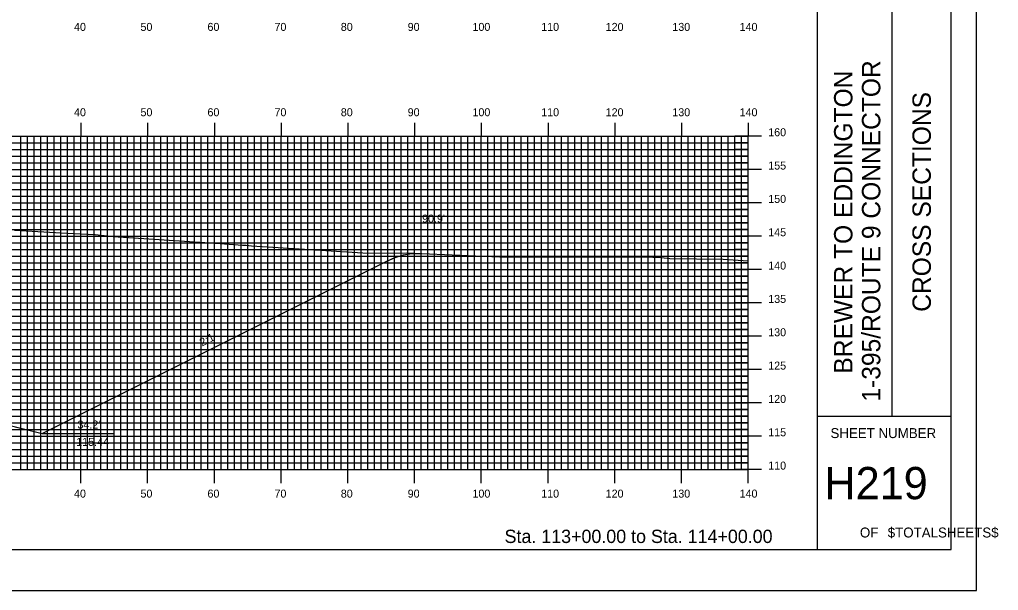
# Model space of a CAD drawing. Extents: x 1770448 to 1770792, y 442591 to 442811.
# Drawn here: x 1770644.9 to 1770791.5, y 442590.5 to 442676.2 of the extents above; entities that cross this region are included whole.
import ezdxf

# ---------------------------------------------------------------- set-up
doc = ezdxf.new("R2010")
doc.units = 0
for name, color, linetype in [('ANNOTATION', 7, 'Continuous'), ('BORDER', 7, 'Continuous'), ('D_Roadway_Centerline', 7, 'Continuous'), ('D_Roadway_SlopeLines', 7, 'Continuous'), ('D_Text_Standard', 7, 'Continuous'), ('H_V ANNOTATION', 7, 'Continuous'), ('MAJOR', 7, 'Continuous'), ('MINOR', 7, 'Continuous'), ('PDRAIN', 7, 'Continuous'), ('PLOT BOUNDARY', 7, 'Continuous'), ('S_Roadway_Centerline', 7, 'Continuous')]:
    doc.layers.add(name, color=color, linetype=linetype)

msp = doc.modelspace()

# ---------------------------------------------------------------- linework, layer by layer
at = {"layer": 'BORDER'}
for p, q in [((1770764.44, 442596.67), (1770764.44, 442806.67)), ((1770775.62, 442616.67), (1770775.62, 442686.67)), ((1770764.44, 442616.67), (1770784.44, 442616.67))]:
    msp.add_line(p, q, dxfattribs=at)
msp.add_lwpolyline([(1770464.44, 442596.67), (1770784.44, 442596.67), (1770784.44, 442806.67), (1770464.44, 442806.67)], close=True, dxfattribs=at)
at = {"layer": 'D_Roadway_Centerline'}
msp.add_lwpolyline([(1770644.21, 442615.1), (1770648.22, 442614.1), (1770653.42, 442616.7), (1770699.89, 442639.94), (1770701.1, 442640.47), (1770701.14, 442640.48), (1770702.39, 442640.86), (1770703.34, 442641.01), (1770703.64, 442641.06), (1770704.04, 442641.07), (1770704.89, 442641.1)], dxfattribs=at)
at = {"layer": 'D_Roadway_SlopeLines'}
for points in [[(1770648.22, 442614.1), (1770699.89, 442639.94), (1770701.14, 442640.48), (1770702.39, 442640.86), (1770703.64, 442641.06), (1770704.89, 442641.1)], [(1770634.04, 442617.65), (1770648.22, 442614.1)]]:
    msp.add_lwpolyline(points, dxfattribs=at)
at = {"layer": 'MAJOR'}
for p, q in [((1770654.04, 442660.67), (1770654.04, 442658.67)), ((1770664.04, 442660.67), (1770664.04, 442658.67)), ((1770674.04, 442660.67), (1770674.04, 442658.67)), ((1770684.04, 442660.67), (1770684.04, 442658.67)), ((1770694.04, 442660.67), (1770694.04, 442658.67)), ((1770704.04, 442660.67), (1770704.04, 442658.67)), ((1770714.04, 442660.67), (1770714.04, 442658.67)), ((1770724.04, 442660.67), (1770724.04, 442658.67)), ((1770734.04, 442660.67), (1770734.04, 442658.67)), ((1770744.04, 442660.67), (1770744.04, 442658.67)), ((1770754.04, 442660.67), (1770754.04, 442658.67)), ((1770474.04, 442658.67), (1770754.04, 442658.67)), ((1770474.04, 442658.67), (1770754.04, 442658.67)), ((1770654.04, 442608.67), (1770654.04, 442658.67)), ((1770664.04, 442608.67), (1770664.04, 442658.67)), ((1770674.04, 442608.67), (1770674.04, 442658.67)), ((1770684.04, 442608.67), (1770684.04, 442658.67)), ((1770694.04, 442608.67), (1770694.04, 442658.67)), ((1770704.04, 442608.67), (1770704.04, 442658.67)), ((1770714.04, 442608.67), (1770714.04, 442658.67)), ((1770724.04, 442608.67), (1770724.04, 442658.67)), ((1770734.04, 442608.67), (1770734.04, 442658.67)), ((1770744.04, 442608.67), (1770744.04, 442658.67)), ((1770756.05, 442658.67), (1770752.04, 442658.67)), ((1770754.04, 442608.67), (1770754.04, 442658.67)), ((1770754.04, 442608.67), (1770754.04, 442658.67)), ((1770474.04, 442653.67), (1770754.04, 442653.67)), ((1770756.05, 442653.67), (1770752.04, 442653.67)), ((1770474.04, 442648.67), (1770754.04, 442648.67)), ((1770756.05, 442648.67), (1770752.04, 442648.67)), ((1770474.04, 442643.67), (1770754.04, 442643.67)), ((1770756.05, 442643.67), (1770752.04, 442643.67)), ((1770474.04, 442638.67), (1770754.04, 442638.67)), ((1770756.05, 442638.67), (1770752.04, 442638.67)), ((1770474.04, 442633.67), (1770754.04, 442633.67)), ((1770756.05, 442633.67), (1770752.04, 442633.67)), ((1770474.04, 442628.67), (1770754.04, 442628.67)), ((1770756.05, 442628.67), (1770752.04, 442628.67)), ((1770474.04, 442623.67), (1770754.04, 442623.67)), ((1770756.05, 442623.67), (1770752.04, 442623.67)), ((1770474.04, 442618.67), (1770754.04, 442618.67)), ((1770756.05, 442618.67), (1770752.04, 442618.67)), ((1770474.04, 442613.67), (1770754.04, 442613.67)), ((1770756.05, 442613.67), (1770752.04, 442613.67)), ((1770474.04, 442608.67), (1770754.04, 442608.67)), ((1770474.04, 442608.67), (1770754.04, 442608.67)), ((1770654.04, 442606.66), (1770654.04, 442608.67)), ((1770664.04, 442606.66), (1770664.04, 442608.67)), ((1770674.04, 442606.66), (1770674.04, 442608.67)), ((1770684.04, 442606.66), (1770684.04, 442608.67)), ((1770694.04, 442606.66), (1770694.04, 442608.67)), ((1770704.04, 442606.66), (1770704.04, 442608.67)), ((1770714.04, 442606.66), (1770714.04, 442608.67)), ((1770724.04, 442606.66), (1770724.04, 442608.67)), ((1770734.04, 442606.66), (1770734.04, 442608.67)), ((1770744.04, 442606.66), (1770744.04, 442608.67)), ((1770756.05, 442608.67), (1770752.04, 442608.67)), ((1770754.04, 442606.66), (1770754.04, 442608.67))]:
    msp.add_line(p, q, dxfattribs=at)
at = {"layer": 'MINOR'}
for p, q in [((1770645.04, 442608.67), (1770645.04, 442658.67)), ((1770646.04, 442608.67), (1770646.04, 442658.67)), ((1770647.04, 442608.67), (1770647.04, 442658.67)), ((1770648.04, 442608.67), (1770648.04, 442658.67)), ((1770649.04, 442608.67), (1770649.04, 442658.67)), ((1770650.04, 442608.67), (1770650.04, 442658.67)), ((1770651.04, 442608.67), (1770651.04, 442658.67)), ((1770652.04, 442608.67), (1770652.04, 442658.67)), ((1770653.04, 442608.67), (1770653.04, 442658.67)), ((1770655.04, 442608.67), (1770655.04, 442658.67)), ((1770656.04, 442608.67), (1770656.04, 442658.67)), ((1770657.04, 442608.67), (1770657.04, 442658.67)), ((1770658.04, 442608.67), (1770658.04, 442658.67)), ((1770659.04, 442608.67), (1770659.04, 442658.67)), ((1770660.04, 442608.67), (1770660.04, 442658.67)), ((1770661.04, 442608.67), (1770661.04, 442658.67)), ((1770662.04, 442608.67), (1770662.04, 442658.67)), ((1770663.04, 442608.67), (1770663.04, 442658.67)), ((1770665.04, 442608.67), (1770665.04, 442658.67)), ((1770666.04, 442608.67), (1770666.04, 442658.67)), ((1770667.04, 442608.67), (1770667.04, 442658.67)), ((1770668.04, 442608.67), (1770668.04, 442658.67)), ((1770669.04, 442608.67), (1770669.04, 442658.67)), ((1770670.04, 442608.67), (1770670.04, 442658.67)), ((1770671.04, 442608.67), (1770671.04, 442658.67)), ((1770672.04, 442608.67), (1770672.04, 442658.67)), ((1770673.04, 442608.67), (1770673.04, 442658.67)), ((1770675.04, 442608.67), (1770675.04, 442658.67)), ((1770676.04, 442608.67), (1770676.04, 442658.67)), ((1770677.04, 442608.67), (1770677.04, 442658.67)), ((1770678.04, 442608.67), (1770678.04, 442658.67)), ((1770679.04, 442608.67), (1770679.04, 442658.67)), ((1770680.04, 442608.67), (1770680.04, 442658.67)), ((1770681.04, 442608.67), (1770681.04, 442658.67)), ((1770682.04, 442608.67), (1770682.04, 442658.67)), ((1770683.04, 442608.67), (1770683.04, 442658.67)), ((1770685.04, 442608.67), (1770685.04, 442658.67)), ((1770686.04, 442608.67), (1770686.04, 442658.67)), ((1770687.04, 442608.67), (1770687.04, 442658.67)), ((1770688.04, 442608.67), (1770688.04, 442658.67)), ((1770689.04, 442608.67), (1770689.04, 442658.67)), ((1770690.04, 442608.67), (1770690.04, 442658.67)), ((1770691.04, 442608.67), (1770691.04, 442658.67)), ((1770692.04, 442608.67), (1770692.04, 442658.67)), ((1770693.04, 442608.67), (1770693.04, 442658.67)), ((1770695.04, 442608.67), (1770695.04, 442658.67)), ((1770696.04, 442608.67), (1770696.04, 442658.67)), ((1770697.04, 442608.67), (1770697.04, 442658.67)), ((1770698.04, 442608.67), (1770698.04, 442658.67)), ((1770699.04, 442608.67), (1770699.04, 442658.67)), ((1770700.04, 442608.67), (1770700.04, 442658.67)), ((1770701.04, 442608.67), (1770701.04, 442658.67)), ((1770702.04, 442608.67), (1770702.04, 442658.67)), ((1770703.04, 442608.67), (1770703.04, 442658.67)), ((1770705.04, 442608.67), (1770705.04, 442658.67)), ((1770706.04, 442608.67), (1770706.04, 442658.67)), ((1770707.04, 442608.67), (1770707.04, 442658.67)), ((1770708.04, 442608.67), (1770708.04, 442658.67)), ((1770709.04, 442608.67), (1770709.04, 442658.67)), ((1770710.04, 442608.67), (1770710.04, 442658.67)), ((1770711.04, 442608.67), (1770711.04, 442658.67)), ((1770712.04, 442608.67), (1770712.04, 442658.67)), ((1770713.04, 442608.67), (1770713.04, 442658.67)), ((1770715.04, 442608.67), (1770715.04, 442658.67)), ((1770716.04, 442608.67), (1770716.04, 442658.67)), ((1770717.04, 442608.67), (1770717.04, 442658.67)), ((1770718.04, 442608.67), (1770718.04, 442658.67)), ((1770719.04, 442608.67), (1770719.04, 442658.67)), ((1770720.04, 442608.67), (1770720.04, 442658.67)), ((1770721.04, 442608.67), (1770721.04, 442658.67)), ((1770722.04, 442608.67), (1770722.04, 442658.67)), ((1770723.04, 442608.67), (1770723.04, 442658.67)), ((1770725.04, 442608.67), (1770725.04, 442658.67)), ((1770726.04, 442608.67), (1770726.04, 442658.67)), ((1770727.04, 442608.67), (1770727.04, 442658.67)), ((1770728.04, 442608.67), (1770728.04, 442658.67)), ((1770729.04, 442608.67), (1770729.04, 442658.67)), ((1770730.04, 442608.67), (1770730.04, 442658.67)), ((1770731.04, 442608.67), (1770731.04, 442658.67)), ((1770732.04, 442608.67), (1770732.04, 442658.67)), ((1770733.04, 442608.67), (1770733.04, 442658.67)), ((1770735.04, 442608.67), (1770735.04, 442658.67)), ((1770736.04, 442608.67), (1770736.04, 442658.67)), ((1770737.04, 442608.67), (1770737.04, 442658.67)), ((1770738.04, 442608.67), (1770738.04, 442658.67)), ((1770739.04, 442608.67), (1770739.04, 442658.67)), ((1770740.04, 442608.67), (1770740.04, 442658.67)), ((1770741.04, 442608.67), (1770741.04, 442658.67)), ((1770742.04, 442608.67), (1770742.04, 442658.67)), ((1770743.04, 442608.67), (1770743.04, 442658.67)), ((1770745.04, 442608.67), (1770745.04, 442658.67)), ((1770746.04, 442608.67), (1770746.04, 442658.67)), ((1770747.04, 442608.67), (1770747.04, 442658.67)), ((1770748.04, 442608.67), (1770748.04, 442658.67)), ((1770749.04, 442608.67), (1770749.04, 442658.67)), ((1770750.04, 442608.67), (1770750.04, 442658.67)), ((1770751.04, 442608.67), (1770751.04, 442658.67)), ((1770752.04, 442608.67), (1770752.04, 442658.67)), ((1770753.04, 442608.67), (1770753.04, 442658.67)), ((1770474.04, 442657.67), (1770754.04, 442657.67)), ((1770754.04, 442657.67), (1770752.04, 442657.67)), ((1770474.04, 442656.67), (1770754.04, 442656.67)), ((1770474.04, 442655.67), (1770754.04, 442655.67)), ((1770754.04, 442656.67), (1770752.04, 442656.67)), ((1770754.04, 442655.67), (1770752.04, 442655.67)), ((1770474.04, 442654.67), (1770754.04, 442654.67)), ((1770754.04, 442654.67), (1770752.04, 442654.67)), ((1770474.04, 442652.67), (1770754.04, 442652.67)), ((1770754.04, 442652.67), (1770752.04, 442652.67)), ((1770474.04, 442651.67), (1770754.04, 442651.67)), ((1770754.04, 442651.67), (1770752.04, 442651.67)), ((1770474.04, 442650.67), (1770754.04, 442650.67)), ((1770474.04, 442649.67), (1770754.04, 442649.67)), ((1770754.04, 442650.67), (1770752.04, 442650.67)), ((1770754.04, 442649.67), (1770752.04, 442649.67)), ((1770474.04, 442647.67), (1770754.04, 442647.67)), ((1770474.04, 442646.67), (1770754.04, 442646.67)), ((1770754.04, 442647.67), (1770752.04, 442647.67)), ((1770754.04, 442646.67), (1770752.04, 442646.67)), ((1770474.04, 442645.67), (1770754.04, 442645.67)), ((1770754.04, 442645.67), (1770752.04, 442645.67)), ((1770474.04, 442644.67), (1770754.04, 442644.67)), ((1770754.04, 442644.67), (1770752.04, 442644.67)), ((1770474.04, 442642.67), (1770754.04, 442642.67)), ((1770754.04, 442642.67), (1770752.04, 442642.67)), ((1770474.04, 442641.67), (1770754.04, 442641.67)), ((1770474.04, 442640.67), (1770754.04, 442640.67)), ((1770754.04, 442641.67), (1770752.04, 442641.67)), ((1770754.04, 442640.67), (1770752.04, 442640.67)), ((1770474.04, 442639.67), (1770754.04, 442639.67)), ((1770754.04, 442639.67), (1770752.04, 442639.67)), ((1770474.04, 442637.67), (1770754.04, 442637.67)), ((1770754.04, 442637.67), (1770752.04, 442637.67)), ((1770474.04, 442636.67), (1770754.04, 442636.67)), ((1770754.04, 442636.67), (1770752.04, 442636.67)), ((1770474.04, 442635.67), (1770754.04, 442635.67)), ((1770754.04, 442635.67), (1770752.04, 442635.67)), ((1770474.04, 442634.67), (1770754.04, 442634.67)), ((1770754.04, 442634.67), (1770752.04, 442634.67)), ((1770474.04, 442632.67), (1770754.04, 442632.67)), ((1770754.04, 442632.67), (1770752.04, 442632.67)), ((1770474.04, 442631.67), (1770754.04, 442631.67)), ((1770474.04, 442630.67), (1770754.04, 442630.67)), ((1770754.04, 442631.67), (1770752.04, 442631.67)), ((1770754.04, 442630.67), (1770752.04, 442630.67)), ((1770474.04, 442629.67), (1770754.04, 442629.67)), ((1770754.04, 442629.67), (1770752.04, 442629.67)), ((1770474.04, 442627.67), (1770754.04, 442627.67)), ((1770754.04, 442627.67), (1770752.04, 442627.67)), ((1770474.04, 442626.67), (1770754.04, 442626.67)), ((1770754.04, 442626.67), (1770752.04, 442626.67)), ((1770474.04, 442625.67), (1770754.04, 442625.67)), ((1770474.04, 442624.67), (1770754.04, 442624.67)), ((1770754.04, 442625.67), (1770752.04, 442625.67)), ((1770754.04, 442624.67), (1770752.04, 442624.67)), ((1770474.04, 442622.67), (1770754.04, 442622.67)), ((1770474.04, 442621.67), (1770754.04, 442621.67)), ((1770754.04, 442622.67), (1770752.04, 442622.67)), ((1770754.04, 442621.67), (1770752.04, 442621.67)), ((1770474.04, 442620.67), (1770754.04, 442620.67)), ((1770754.04, 442620.67), (1770752.04, 442620.67)), ((1770474.04, 442619.67), (1770754.04, 442619.67)), ((1770754.04, 442619.67), (1770752.04, 442619.67)), ((1770474.04, 442617.67), (1770754.04, 442617.67)), ((1770754.04, 442617.67), (1770752.04, 442617.67)), ((1770474.04, 442616.67), (1770754.04, 442616.67)), ((1770474.04, 442615.67), (1770754.04, 442615.67)), ((1770754.04, 442616.67), (1770752.04, 442616.67)), ((1770754.04, 442615.67), (1770752.04, 442615.67)), ((1770474.04, 442614.67), (1770754.04, 442614.67)), ((1770754.04, 442614.67), (1770752.04, 442614.67)), ((1770474.04, 442612.67), (1770754.04, 442612.67)), ((1770474.04, 442611.67), (1770754.04, 442611.67)), ((1770754.04, 442612.67), (1770752.04, 442612.67)), ((1770754.04, 442611.67), (1770752.04, 442611.67)), ((1770474.04, 442610.67), (1770754.04, 442610.67)), ((1770754.04, 442610.67), (1770752.04, 442610.67)), ((1770474.04, 442609.67), (1770754.04, 442609.67)), ((1770754.04, 442609.67), (1770752.04, 442609.67))]:
    msp.add_line(p, q, dxfattribs=at)
at = {"layer": 'PDRAIN'}
msp.add_line((1770648.22, 442614.1), (1770658.99, 442614.1), dxfattribs=at)
at = {"layer": 'PLOT BOUNDARY'}
msp.add_lwpolyline([(1770448.25, 442590.55), (1770788.25, 442590.55), (1770788.25, 442810.55), (1770448.25, 442810.55)], close=True, dxfattribs=at)
at = {"layer": 'S_Roadway_Centerline'}
msp.add_lwpolyline([(1770644.07, 442644.56), (1770651.96, 442644.15), (1770656.19, 442643.91), (1770658.86, 442643.61), (1770674.89, 442642.57), (1770678.24, 442642.32), (1770678.79, 442642.31), (1770679.62, 442642.24), (1770697.11, 442641.11), (1770702.85, 442641.2), (1770712, 442640.76), (1770716.81, 442640.57), (1770726.55, 442640.56), (1770736.12, 442640.58), (1770738.45, 442640.58), (1770741.05, 442640.46), (1770742.28, 442640.35), (1770750.29, 442640.23), (1770754.04, 442639.97)], dxfattribs=at)

# ---------------------------------------------------------------- texts
at = {"layer": 'ANNOTATION'}
msp.add_text('2:1', height=1.2, rotation=26.5649, dxfattribs=at).set_placement((1770672.2, 442627.13))
for s, p in [("34.2'", (1770653.53, 442614.83)), ('115.44', (1770653.34, 442612.23))]:
    msp.add_text(s, height=1.2, dxfattribs=at).set_placement(p)
at = {"layer": 'BORDER'}
for s, p in [('1-395/ROUTE 9 CONNECTOR', (1770773.84, 442618.87)), ('BREWER TO EDDINGTON', (1770769.66, 442623.07)), ('CROSS SECTIONS', (1770781.41, 442632.34))]:
    msp.add_text(s, height=2.7557, rotation=90, dxfattribs=at).set_placement(p)
for s, height, p in [('SHEET NUMBER', 1.4905, (1770766.37, 442613.4)), ('H219', 4.839, (1770765.47, 442604.23)), ('OF', 1.491, (1770770.78, 442598.49)), ('$TOTALSHEETS$', 1.4905, (1770774.95, 442598.49))]:
    msp.add_text(s, height=height, dxfattribs=at).set_placement(p)
at = {"layer": 'D_Text_Standard'}
msp.add_text("90.9'", height=1.2, dxfattribs=at).set_placement((1770705.17, 442645.72))
at = {"layer": 'H_V ANNOTATION'}
for s, height, p in [('40', 1.2, (1770653.01, 442674.47)), ('50', 1.2, (1770662.97, 442674.47)), ('60', 1.2, (1770673.01, 442674.47)), ('70', 1.2, (1770683.05, 442674.47)), ('80', 1.2, (1770692.99, 442674.47)), ('90', 1.2, (1770703.01, 442674.47)), ('100', 1.2, (1770712.72, 442674.47)), ('110', 1.2, (1770723.02, 442674.47)), ('120', 1.2, (1770732.68, 442674.47)), ('130', 1.2, (1770742.67, 442674.47)), ('140', 1.2, (1770752.75, 442674.47)), ('40', 1.2, (1770653.01, 442661.67)), ('50', 1.2, (1770662.97, 442661.67)), ('60', 1.2, (1770673.01, 442661.67)), ('70', 1.2, (1770683.05, 442661.67)), ('80', 1.2, (1770692.99, 442661.67)), ('90', 1.2, (1770703.01, 442661.67)), ('100', 1.2, (1770712.72, 442661.67)), ('110', 1.2, (1770723.02, 442661.67)), ('120', 1.2, (1770732.68, 442661.67)), ('130', 1.2, (1770742.67, 442661.67)), ('140', 1.2, (1770752.75, 442661.67)), ('160', 1.2, (1770757.04, 442658.67)), ('155', 1.2, (1770757.04, 442653.67)), ('150', 1.2, (1770757.04, 442648.67)), ('145', 1.2, (1770757.04, 442643.67)), ('140', 1.2, (1770757.04, 442638.67)), ('135', 1.2, (1770757.04, 442633.67)), ('130', 1.2, (1770757.04, 442628.67)), ('125', 1.2, (1770757.04, 442623.67)), ('120', 1.2, (1770757.04, 442618.67)), ('115', 1.2, (1770757.04, 442613.67)), ('110', 1.2, (1770757.04, 442608.67)), ('40', 1.2, (1770653.01, 442604.47)), ('50', 1.2, (1770662.97, 442604.47)), ('60', 1.2, (1770673.01, 442604.47)), ('70', 1.2, (1770683.05, 442604.47)), ('80', 1.2, (1770692.99, 442604.47)), ('90', 1.2, (1770703.01, 442604.47)), ('100', 1.2, (1770712.72, 442604.47)), ('110', 1.2, (1770723.02, 442604.47)), ('120', 1.2, (1770732.68, 442604.47)), ('130', 1.2, (1770742.67, 442604.47)), ('140', 1.2, (1770752.75, 442604.47)), ('Sta. 113+00.00 to Sta. 114+00.00', 2.0004, (1770717.53, 442597.66))]:
    msp.add_text(s, height=height, dxfattribs=at).set_placement(p)

doc.saveas('drawing.dxf')
